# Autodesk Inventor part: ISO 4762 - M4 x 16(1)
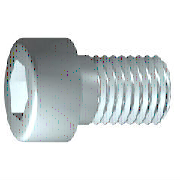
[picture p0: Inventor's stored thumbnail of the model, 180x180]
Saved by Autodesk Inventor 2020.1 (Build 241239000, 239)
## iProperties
Created: 2019-01
Part Number: ISO 4762 - M4 x 16(1)
Material: Edelstahl, 440C
Description: Innensechskantschraube
Document SubType Name: Modeling
Standard: ISO 4762
Designer: lutzd
Standard Revision: Fourth edition 2004-03-01
Standards Organization: ISO
Language: de-DE
Size Designation: M4 x 16
Categories: <MemberInstance><Categories><Category DisplayName="Verbindungselemente" InternalName="e4da775c-781d-43d5-af7c-5136215cf5a6" Mnemonic="FSTN"><Category DisplayNam
Mass: 2.59293 g
Surface Area: 3.81118 cm^2
Volume: 0.334572 cm^3
Density: 7.75 g/cm^3
Appearance: Halbpoliert
IsCustomPart: 0
Author: lutzd
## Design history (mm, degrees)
body "Solid1"
sketch "Skizze1"
  geometry: L1 (-1, 0)-(16, 0); L2 (16, 0)-(16, 2); L3 (16, 2)-(1.75, 2); L4 (1.75, 2)-(1.32, 2); L5 (1.32, 2)-(0, 2); L6 (0, 2)-(0, 3.5); L7 (0, 3.5)-(-4, 3.5); L8 (-4, 3.5)-(-4, 1.732); L9 (-4, 1.732)-(-2, 1.732); L10 (-2, 1.732)-(-1, 0); L11 (-8, 0)-(20, 0) reference; L12 (0, -0.7)-(0, 4.2) reference; L13 (1.75, 2)-(0, 2)
  constraints: 22 end point, 6 parallel, 2 collinear, 2 perpendicular, 1 horizontal, 1 point on line
  dimensions: "d1" = 14.25 distance from line of L3.end L2 (= GEL); "d2" = 0.42952 distance of L4.end L3.end (computed from GAL); "d3" = 4 distance between parallel lines of L8 L6 (= KOH); "d4" = 2 distance of L8.end L9.end (= INTI); "d5" = 60 deg angle of L10 L1; "d6" = 4 diameter of L3 L1 (= GD); "d7" = 4 diameter of L5 L1 (= BDM); "d8" = 3.4641 diameter of L9 L1 (= 1.1547 x SW); "d9" = 7 diameter of L7 L1 (= KOD); "d26" = 16 distance between parallel lines of L12 L2 (= NLG)
workplane "Work Plane1"
fillet "Fillet2" dims "d30" = 0.1 (= R)
revolve "Körper" stored, may be unused: angle "d10" = 90 deg
sketch "Skizze2"
  geometry: L1 (0, -4.9)-(0, 4.9) reference; L2 (-4.9, 0)-(4.9, 0) reference; L3 (1.732, 0)-(0.866, -1.5); L4 (0.866, -1.5)-(-0.866, -1.5); L5 (-0.866, -1.5)-(-1.732, 0); L6 (-1.732, 0)-(-0.866, 1.5); L7 (-0.866, 1.5)-(0.866, 1.5); L8 (0.866, 1.5)-(1.732, 0); 2 further points
  constraints: 12 end point, 1 coincident, 1 horizontal alignment, 1 point on line, 12 other
extrude "Loch" join sketch "Skizze2" stored distance "d11" = 10; taper "d12" = 0 deg
fillet "Rundung1" dims "d17" = 0.4 (= RR)
feature "Gewinde" dims "d13" = 14.25 (= GEL), "d14" = 0
chamfer "Fase1" distance "d15" = 0.42941 (= -0.5 x SPD + 0.5 x GD); stored, may be unused: second distance "d16" = 0.42941 (= GUL), angle "d27" = 45 deg
other parameters: "GD" = 4 [user parameter; used in 2 equation terms], "NLG" = 16 [user parameter; used in 1 equation term], "GEL" = 14.25 [user parameter; used in 2 equation terms], "KOD" = 7 [user parameter; used in 1 equation term], "KOH" = 4 [user parameter; used in 1 equation term], "INTI" = 2 [user parameter; used in 1 equation term], "GAL" = 0.42941 (= 0.61345 x PTC) [user parameter; used in 1 equation term], "GUL" = 0.42941 (= 0.61345 x PTC) [user parameter; used in 1 equation term], "BDM" = 4 (= NND) [user parameter; used in 1 equation term], "SW" = 3 [user parameter; used in 2 equation terms], "RR" = 0.4 [user parameter; used in 1 equation term], "SPD" = 3.14117 (= NND - 1.2269 x PTC) [user parameter; used in 1 equation term], "d19" = 0, "d28" = 0, "d29" = 0, "R" = 0.1 [user parameter; used in 1 equation term], "TOA" = 30 deg [user parameter], "GD1" = 3.14117 (= THREADDIA - 1.2269 x PTC) [user parameter], "THREADDIA" = 4 [user parameter; used in 1 equation term], "FAWI" = 45 deg [user parameter], "TPU" = 14.28571 (computed from PTC) [user parameter], "PTC" = 0.7 [user parameter; used in 5 equation terms], "NND" = 4 [user parameter; used in 2 equation terms], "E0" = 3.465 (= 1.155 x SW) [user parameter]
